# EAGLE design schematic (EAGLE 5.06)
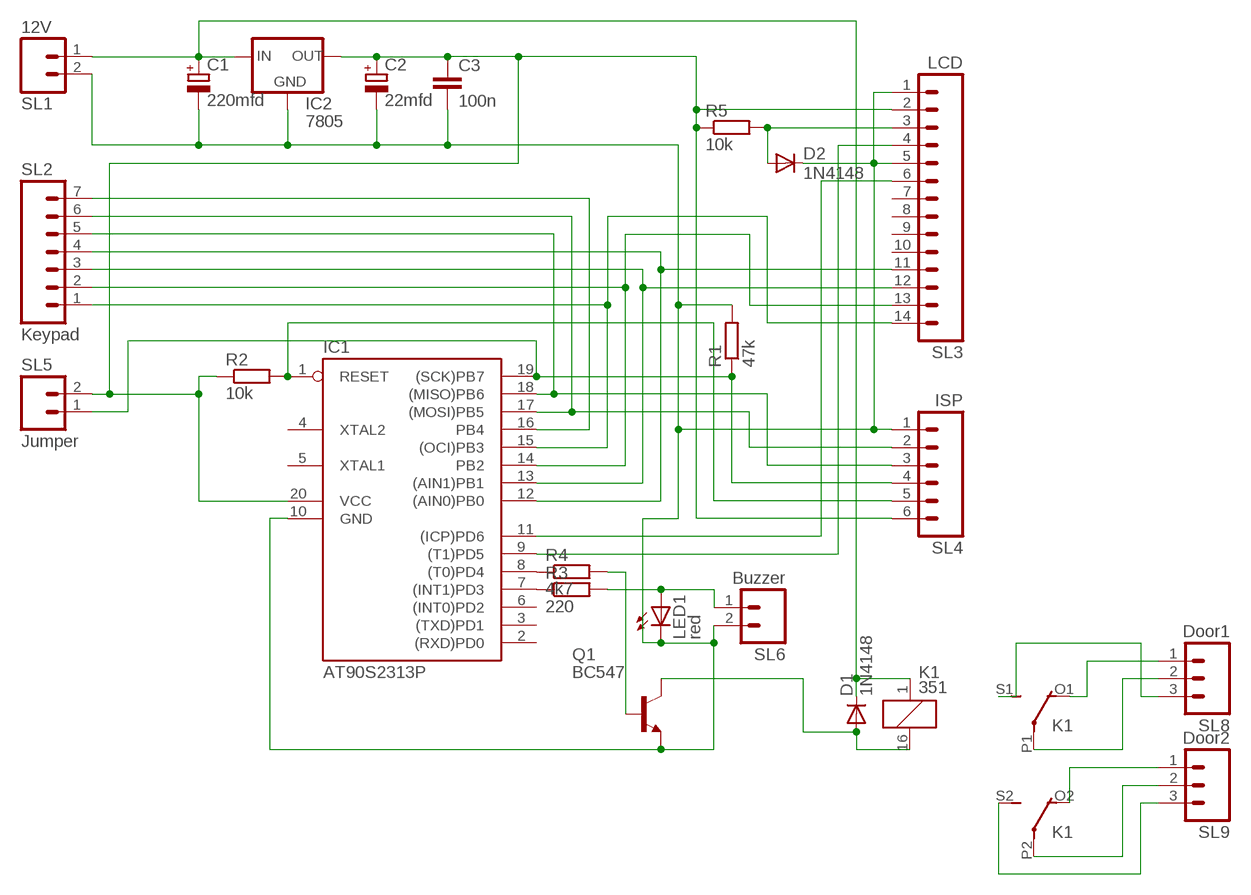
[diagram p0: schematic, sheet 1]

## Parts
C1  220mfd  CPOL-EUE2.5-5  [E2,5-5]
C2  22mfd  CPOL-EUE2.5-5  [E2,5-5]
C3  100n  C-EU050-025X075  [C050-025X075]
D1  1N4148  [DO35-10]
D2  1N4148  [DO35-10]
IC1  AT90S2313P  [DIL20]
IC2  7805  78XXS  [78XXS]
K1  351  [351]
LED1  red  LED3MM  [LED3MM]
Q1  BC547  [TO92]
R1  47k  R-EU_0204/7  [0204/7]
R2  10k  R-EU_0204/7  [0204/7]
R3  220  R-EU_0204/7  [0204/7]
R4  4k7  R-EU_0204/7  [0204/7]
R5  10k  R-EU_0204/7  [0204/7]
SL1  12V  M02  [02P]
SL2  Keypad  M07  [07P]
SL3  LCD  M14  [14P]
SL4  ISP  M06  [06P]
SL5  Jumper  M02  [02P]
SL6  Buzzer  M02  [02P]
SL8  Door1  M03  [03P]
SL9  Door2  M03  [03P]

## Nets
N$1: C1.- C2.- C3.2 D2.C IC1.10(GND) IC2.GND LED1.K(C) Q1.1(E) R1.2 SL1.2 SL3.1 SL4.1 SL6.2
N$2: IC1.9((T1)PD5) SL3.4
N$3: IC1.15((OCI)PB3) SL2.1 SL3.14
N$4: IC1.14(PB2) SL2.2 SL3.13
N$5: IC1.13((AIN1)PB1) SL2.3 SL3.12
N$6: IC1.12((AIN0)PB0) SL3.11
N$7: IC1.18((MISO)PB6) SL2.5 SL4.3
N$8: IC1.17((MOSI)PB5) SL2.6 SL4.2
N$9: IC1.16(PB4) SL2.7
N$10: IC1.11((ICP)PD6) SL3.6
N$11: IC1.7((INT1)PD3) R3.1
N$12: IC1.1(RESET) R2.2 SL4.5
N$13: IC1.19((SCK)PB7) R1.1 SL4.4 SL5.1
N$14: LED1.A R3.2 SL6.1
N$16: C2.+ C3.1 IC1.20(VCC) IC2.OUT R2.1 R5.1 SL3.2 SL4.6 SL5.2
N$17: IC1.8((T0)PD4) R4.1
N$18: Q1.2(B) R4.2
N$19: D1.A K1.16 Q1.3(C)
N$20: C1.+ D1.C IC2.IN K1.1 SL1.1
N$21: K1.P1(2:P) SL8.2
N$22: K1.P2(3:P) SL9.2
N$23: K1.O1(2:O) SL8.1
N$24: K1.S1(2:S) SL8.3
N$25: K1.O2(3:O) SL9.1
N$26: K1.S2(3:S) SL9.3
N$28: D2.A R5.2 SL3.3
Unconnected: IC1.2((RXD)PD0) IC1.3((TXD)PD1) IC1.4(XTAL2) IC1.5(XTAL1) IC1.6((INT0)PD2) SL2.4 SL3.5 SL3.7 SL3.8 SL3.9 SL3.10

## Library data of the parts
C1 C2 = resistor:CPOL-EU: POLARIZED CAPACITOR, European symbol
C3 = resistor:C-EU: CAPACITOR, European symbol
D1 D2 = diode:1N4148: DIODE
IC1 = atmel:AT90S2313: MICROCONTROLLER 2 Kbytes FLASH 128 bytes SRAM 128 bytes EEPROM UART
IC2 = v-reg:78XXS: VOLTAGE REGULATOR
K1 = relay:351: RELAY 2 x switch, Omron
LED1 = led:LED: LED
Q1 = transistor-npn:BC547*: NPN Transistor
R1-R5 = resistor:R-EU_: RESISTOR, European symbol
SL1 SL5 SL6 = con-amp-quick:M02: AMP QUICK CONNECTOR
SL2 = con-amp-quick:M07: AMP QUICK CONNECTOR
SL3 = con-amp-quick:M14: AMP QUICK CONNECTOR
SL4 = con-amp-quick:M06: AMP QUICK CONNECTOR
SL8 SL9 = con-amp-quick:M03: AMP QUICK CONNECTOR

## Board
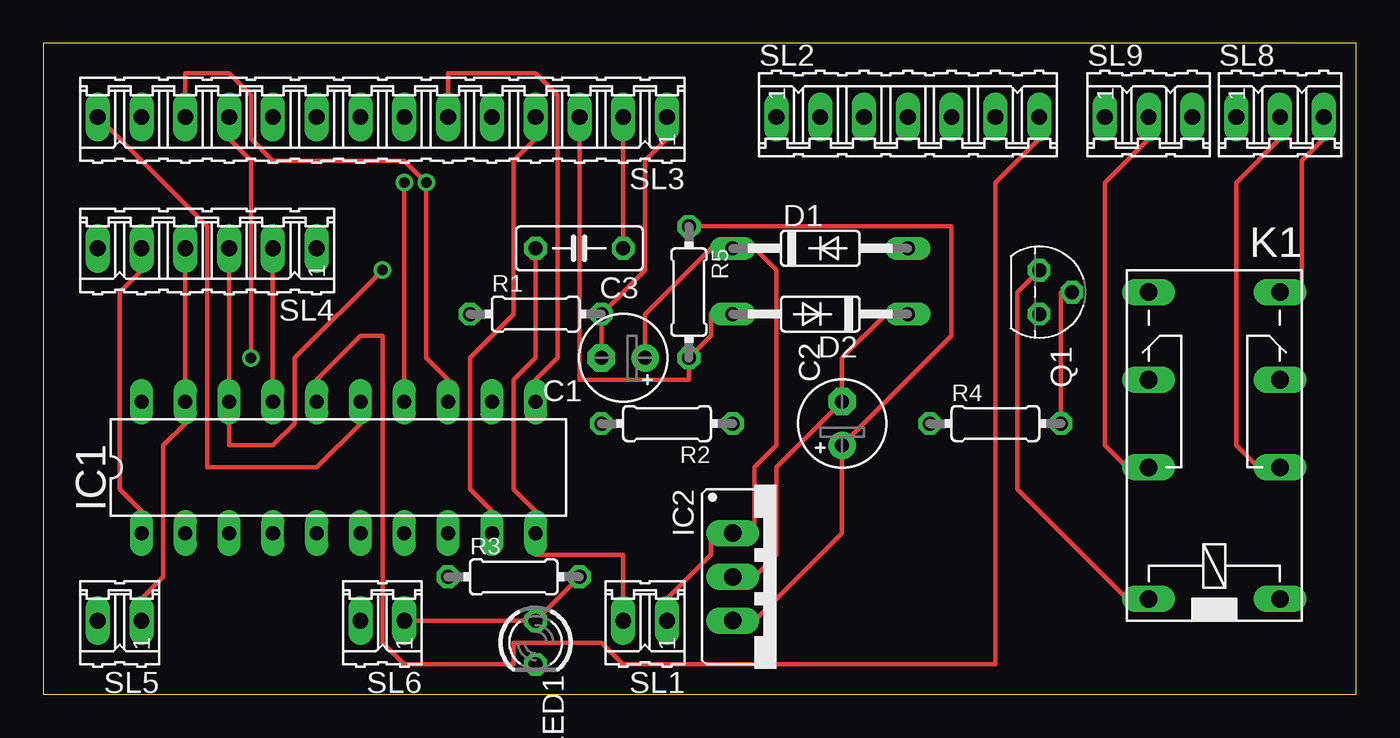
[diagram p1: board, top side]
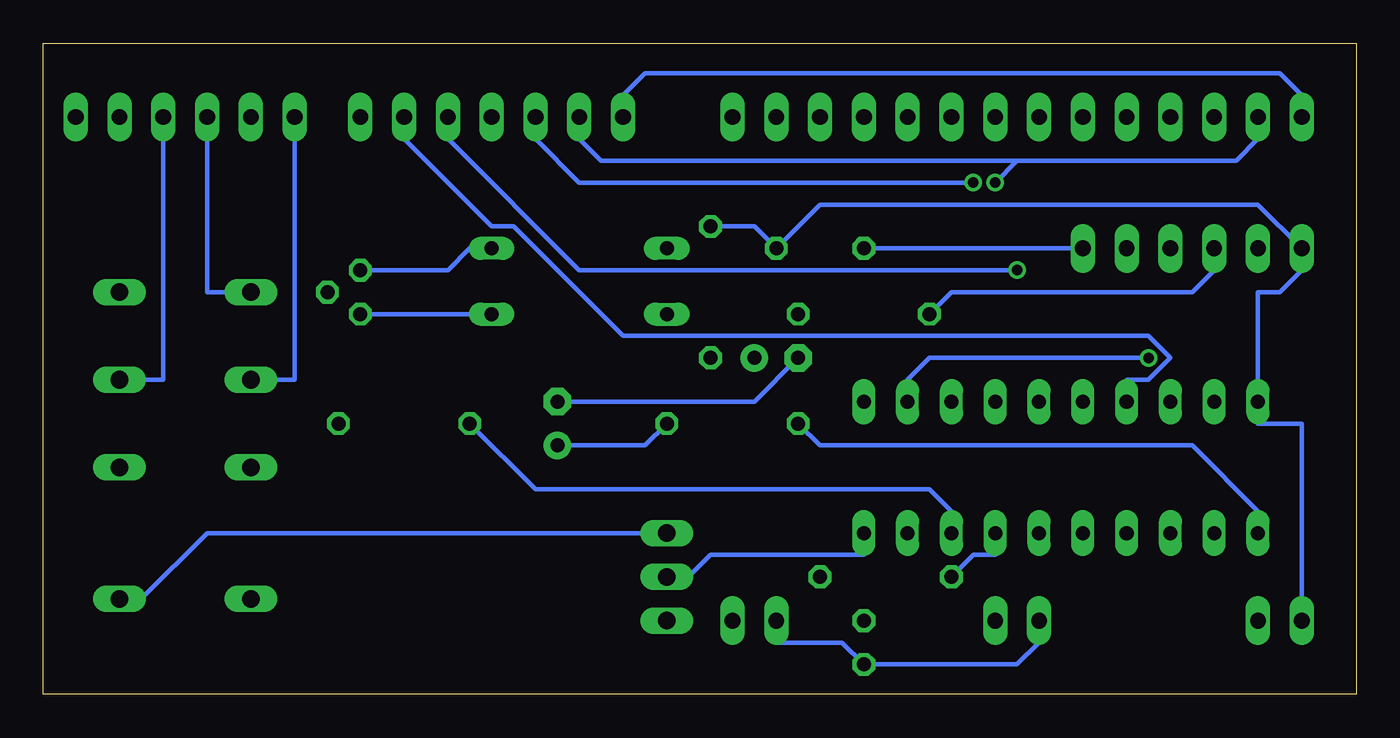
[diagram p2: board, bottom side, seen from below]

Size 76.18 x 37.77 mm. Coordinates in mm from the lower left corner, seen from the top.
Outline: 0,0 76.18,0 76.18,37.77 0,37.77 0,0
Copper layers (1*16): Top 0.035mm / dielectric 1.5mm / Bottom 0.035mm
Design rules "default": minimum track width 10mil, minimum drill 24mil, track to track 8mil, track to pad 8mil, pad to pad 8mil, via to via 8mil, smd to smd 8mil, copper to edge 40mil, drill to drill 8mil, minimum pad ring 10mil, minimum via ring 8mil, stop-mask expansion 4mil, vias tented up to drill 0mil, thermal gap 10mil

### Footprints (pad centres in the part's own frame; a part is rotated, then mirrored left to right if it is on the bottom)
E2,5-5 = drill 0.813 pad 1.6 round: + -1.27,0 | drill 0.813 pad 1.6 octagon: - 1.27,0
C050-025X075 = drill 0.813 octagon: 1 -2.54,0; 2 2.54,0
DO35-10 = drill 0.813 long: A 5.08,0; C -5.08,0
DIL20 = drill 0.813 long: 1 -11.43,-3.81; 2 -8.89,-3.81; 3 -6.35,-3.81; 4 -3.81,-3.81; 5 -1.27,-3.81; 6 1.27,-3.81; 7 3.81,-3.81; 8 6.35,-3.81; 9 8.89,-3.81; 10 11.43,-3.81; 11 11.43,3.81; 12 8.89,3.81; 13 6.35,3.81; 14 3.81,3.81; 15 1.27,3.81; 16 -1.27,3.81; 17 -3.81,3.81; 18 -6.35,3.81; 19 -8.89,3.81; 20 -11.43,3.81
78XXS = drill 1.016 long: GND 0,-2.54; IN -2.54,-2.54; OUT 2.54,-2.54
351 = drill 1.016 long: 1 -3.81,-3.81; 16 -3.81,3.81; O1 8.89,-3.81; O2 8.89,3.81; P1 3.81,-3.81; P2 3.81,3.81; S1 13.97,-3.81; S2 13.97,3.81
LED3MM = drill 0.813 octagon: A -1.27,0; K 1.27,0
TO92 = drill 0.813 octagon: 1 1.27,0; 2 0,1.905; 3 -1.27,0
0204/7 = drill 0.813 octagon: 1 -3.81,0; 2 3.81,0
02P = drill 0.914 long: 1 -1.27,0; 2 1.27,0
07P = drill 0.914 long: 1 -7.62,0; 2 -5.08,0; 3 -2.54,0; 4 0,0; 5 2.54,0; 6 5.08,0; 7 7.62,0
14P = drill 0.914 long: 1 -16.51,0; 2 -13.97,0; 3 -11.43,0; 4 -8.89,0; 5 -6.35,0; 6 -3.81,0; 7 -1.27,0; 8 1.27,0; 9 3.81,0; 10 6.35,0; 11 8.89,0; 12 11.43,0; 13 13.97,0; 14 16.51,0
06P = drill 0.914 long: 1 -6.35,0; 2 -3.81,0; 3 -1.27,0; 4 1.27,0; 5 3.81,0; 6 6.35,0
03P = drill 0.914 long: 1 -2.54,0; 2 0,0; 3 2.54,0

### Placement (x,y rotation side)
C1  33.65,19.52 180 top
C2  46.35,15.71 90 top
C3  31.11,25.87 180 top
D1  45.08,25.87 0 top
D2  45.08,22.06 180 top
IC1  17.14,13.17 0 top
IC2  42.54,6.82 270 top
K1  67.94,9.36 90 top
LED1  28.57,3.01 270 top
Q1  57.78,23.33 270 top
R1  28.57,22.06 0 top
R2  36.19,15.71 180 top
R3  27.3,6.82 0 top
R4  55.24,15.71 0 top
R5  37.46,23.33 270 top
SL1  34.92,4.28 180 top
SL2  50.16,33.49 0 top
SL3  19.68,33.49 180 top
SL4  9.52,25.87 180 top
SL5  4.44,4.28 180 top
SL6  19.68,4.28 180 top
SL8  71.75,33.49 0 top
SL9  64.13,33.49 0 top

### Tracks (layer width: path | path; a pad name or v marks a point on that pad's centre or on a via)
N$1
  Top 0.254: C1.- R1.2 34.92,24.6 34.92,30.95 36.19,32.22 SL3.1 | D2.C 48.89,22.06 46.35,19.52 C2.- 42.54,13.17 42.54,8.09 41.27,6.82 IC2.GND | SL1.2 33.65,8.09 28.57,8.09 IC1.10 28.57,10.63 27.3,11.9 27.3,18.25 28.57,19.52 C3.2
  Bottom 0.254: D2.C Q1.1 | C3.2 SL4.1 | SL1.2 33.65,3.01 29.84,3.01 LED1.K 19.68,1.74 18.41,3.01 SL6.2 | IC2.GND 38.73,6.82 37.46,8.09 28.57,8.09 IC1.10 | C1.- 34.92,16.98 C2.-
N$2
  Top 0.254: IC1.9 26.03,10.63 24.76,11.9 24.76,19.52 27.3,22.06 27.3,30.95 28.57,32.22 SL3.4
N$3
  Top 0.254: SL3.14 9.52,27.14 9.52,13.17 15.87,13.17 18.41,15.71 IC1.15
  Bottom 0.254: SL2.1 42.54,34.76 41.27,36.03 4.44,36.03 3.17,34.76 SL3.14
N$4  (via drill 0.61)
  Top 0.254: IC1.14 v20.95,29.68
  Bottom 0.254: v20.95,29.68 19.68,30.95 | 19.68,30.95 6.98,30.95 5.71,32.22 SL3.13 | 19.68,30.95 43.81,30.95 45.08,32.22 SL2.2
N$5  (via drill 0.61)
  Top 0.254: IC1.13 23.49,18.25 22.22,19.52 v22.22,29.68 20.95,30.95 13.33,30.95 12.06,32.22 12.06,34.76 10.79,36.03 8.25,36.03 SL3.12
  Bottom 0.254: v22.22,29.68 45.08,29.68 47.62,32.22 SL2.3
N$6  (via drill 0.61)
  Top 0.254: v12.06,19.52 12.06,30.95 10.79,32.22 SL3.11
  Bottom 0.254: v12.06,19.52 24.76,19.52 26.03,18.25 IC1.12
N$7  (via drill 0.61)
  Top 0.254: SL4.3 IC1.18 10.79,14.44 13.33,14.44 14.6,15.71 14.6,19.52 v19.68,24.6
  Bottom 0.254: v19.68,24.6 45.08,24.6 52.7,32.22 SL2.5
N$8
  Top 0.254: IC1.17 SL4.2
  Bottom 0.254: SL2.6 55.24,32.22 50.16,27.14 48.89,27.14 42.54,20.79 12.06,20.79 10.79,19.52 12.06,18.25 13.33,18.25 IC1.17
N$9
  Top 0.254: IC1.16 15.87,18.25 18.41,20.79 19.68,20.79 19.68,3.01 20.95,1.74 27.3,1.74 27.3,3.01 32.38,3.01 33.65,1.74 55.24,1.74 55.24,29.68 57.78,32.22 SL2.7
N$10
  Top 0.254: IC1.11 28.57,18.25 29.84,19.52 29.84,34.76 28.57,36.03 23.49,36.03 SL3.6
N$11
  Bottom 0.254: R3.1 22.22,8.09 20.95,8.09 IC1.7
N$12
  Top 0.254: IC1.1 5.71,10.63 4.44,11.9 4.44,23.33 5.71,24.6 SL4.5
  Bottom 0.254: R2.2 31.11,14.44 9.52,14.44 5.71,10.63 IC1.1
N$13
  Top 0.254: SL4.4 IC1.19 8.25,15.71 6.98,14.44 6.98,6.82 5.71,5.55 SL5.1
  Bottom 0.254: R1.1 23.49,23.33 9.52,23.33 8.25,24.6 SL4.4
N$14
  Top 0.254: R3.2 LED1.A SL6.1
N$16
  Top 0.254: C3.1 SL3.2 | IC2.OUT 41.27,4.28 46.35,9.36 C2.+ 52.7,20.79 52.7,27.14 R5.1
  Bottom 0.254: SL5.2 3.17,15.71 5.71,15.71 IC1.20 5.71,23.33 4.44,23.33 3.17,24.6 SL4.6 5.71,28.41 31.11,28.41 C3.1 34.92,27.14 R5.1 | R2.1 41.27,14.44 C2.+
N$17
  Bottom 0.254: R4.1 47.62,11.9 24.76,11.9 23.49,10.63 IC1.8
N$18
  Top 0.254: R4.2 59.05,23.33 Q1.2
N$19
  Top 0.254: Q1.3 56.51,23.33 56.51,11.9 62.86,5.55 K1.16
  Bottom 0.254: Q1.3 52.7,24.6 51.43,25.87 D1.A
N$20
  Top 0.254: C1.+ 34.92,22.06 38.73,25.87 D1.C 41.27,25.87 42.54,24.6 42.54,14.44 41.27,13.17 41.27,9.36 IC2.IN 38.73,9.36 38.73,8.09 36.19,5.55 SL1.1
  Bottom 0.254: K1.1 70.48,5.55 66.67,9.36 IC2.IN
N$21
  Top 0.254: SL8.2 71.75,32.22 69.21,29.68 69.21,14.44 70.48,13.17 K1.P1
N$22
  Top 0.254: SL9.2 64.13,32.22 61.59,29.68 61.59,14.44 62.86,13.17 K1.P2
N$23
  Bottom 0.254: SL8.1 69.21,18.25 K1.O1
N$24
  Top 0.254: SL8.3 74.29,32.22 73.02,30.95 73.02,23.33 K1.S1
N$25
  Bottom 0.254: SL9.1 61.59,18.25 K1.O2
N$26
  Bottom 0.254: SL9.3 66.67,23.33 K1.S2
N$28
  Top 0.254: D2.A 38.73,22.06 38.73,20.79 R5.2 37.46,18.25 31.11,18.25 SL3.3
